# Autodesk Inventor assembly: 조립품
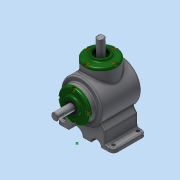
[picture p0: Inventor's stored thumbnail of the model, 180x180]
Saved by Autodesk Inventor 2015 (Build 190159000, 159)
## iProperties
Created: 2018-08
Part Number: 조립품
Document SubType Name: Assembly
Designer: SCD-A18
Author: SCD-A18
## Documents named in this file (14)
- C:\Users\SCD-A18\Desktop\480807V1004\조립품.iam
- C:\Users\SCD-A18\Desktop\480807V1004\본체.ipt
- C:\Users\SCD-A18\Desktop\480807V1004\메인 축.ipt
- 메인 축.ipt
- C:\Users\SCD-A18\Desktop\480807V1004\베어링 6203.ipt
- C:\Users\SCD-A18\Desktop\480807V1004\커버.ipt
- C:\Users\SCD-A18\Desktop\480807V1004\키 5x5.ipt
- C:\Users\SCD-A18\Desktop\480807V1004\메인 베벨기어.ipt
- C:\Users\SCD-A18\Desktop\480807V1004\볼트 M4.ipt
- C:\Users\SCD-A18\Desktop\480807V1004\오일실 17 32 8.ipt
- C:\Users\SCD-A18\Desktop\480807V1004\서브 축.ipt
- 서브 축.ipt
- C:\Users\SCD-A18\Desktop\480807V1004\키 4x4.ipt
- C:\Users\SCD-A18\Desktop\480807V1004\서브 베벨기어.ipt
